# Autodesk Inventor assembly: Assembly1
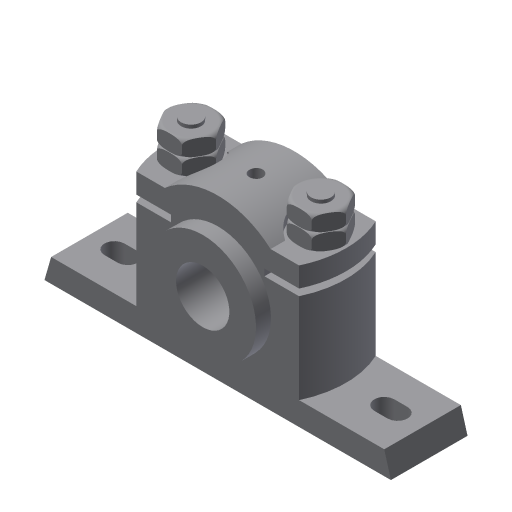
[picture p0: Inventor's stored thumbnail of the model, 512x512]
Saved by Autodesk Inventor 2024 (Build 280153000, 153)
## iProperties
Created: 2016-03
Part Number: Assembly1
Document SubType Name: Assembly
Designer: Sandeep
Author: Sandeep
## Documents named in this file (7)
- D:\PROJECTS\Project 2023\RESOURCES INVENTOR 2024\RESOURCES INVENTOR 2024\Inventor_2023_Part\Inventor_2024_Part\c13_Inv_2024_prt\fig-13-7\Plummer block assy\Assembly1.iam
- D:\PROJECTS\Project 2023\RESOURCES INVENTOR 2024\RESOURCES INVENTOR 2024\Inventor_2023_Part\Inventor_2024_Part\c13_Inv_2024_prt\fig-13-7\Plummer block assy\Casting.ipt
- D:\PROJECTS\Project 2023\RESOURCES INVENTOR 2024\RESOURCES INVENTOR 2024\Inventor_2023_Part\Inventor_2024_Part\c13_Inv_2024_prt\fig-13-7\Plummer block assy\Brasses.ipt
- D:\PROJECTS\Project 2023\RESOURCES INVENTOR 2024\RESOURCES INVENTOR 2024\Inventor_2023_Part\Inventor_2024_Part\c13_Inv_2024_prt\fig-13-7\Plummer block assy\Cap.ipt
- D:\PROJECTS\Project 2023\RESOURCES INVENTOR 2024\RESOURCES INVENTOR 2024\Inventor_2023_Part\Inventor_2024_Part\c13_Inv_2024_prt\fig-13-7\Plummer block assy\Bolt.ipt
- D:\PROJECTS\Project 2023\RESOURCES INVENTOR 2024\RESOURCES INVENTOR 2024\Inventor_2023_Part\Inventor_2024_Part\c13_Inv_2024_prt\fig-13-7\Plummer block assy\Nut.ipt
- D:\PROJECTS\Project 2023\RESOURCES INVENTOR 2024\RESOURCES INVENTOR 2024\Inventor_2023_Part\Inventor_2024_Part\c13_Inv_2024_prt\fig-13-7\Plummer block assy\Lock Nut.ipt
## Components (9 placed, 6 different names)
1. Casting:1 — Mate:1, Mate:2, Insert:1, Insert:2, Angle:1, Angle:2
2. Brasses:1 — Mate:1, Mate:2, Mate:3, Mate:4
3. Cap:1 — Mate:3, Mate:4, Insert:3, Insert:5
4. Bolt:1 — Insert:1, Angle:1
5. Bolt:2 — Insert:2, Angle:2
6. Nut:1 — Insert:3, Insert:4
7. Nut:2 — Insert:5, Insert:6
8. Lock Nut:1 — Insert:4
9. Lock Nut:2 — Insert:6
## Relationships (12: Insert 6, Mate 4, Angle 2)
- Mate:1: Casting:1 ↔ Brasses:1
- Mate:2: Casting:1 ↔ Brasses:1
- Mate:3: Brasses:1 ↔ Cap:1
- Mate:4: Brasses:1 ↔ Cap:1
- Insert:1: Casting:1 ↔ Bolt:1
- Insert:2: Casting:1 ↔ Bolt:2
- Angle:1: Casting:1 ↔ Bolt:1
- Angle:2: Casting:1 ↔ Bolt:2
- Insert:3: Cap:1 ↔ Nut:1
- Insert:4: Nut:1 ↔ Lock Nut:1
- Insert:5: Cap:1 ↔ Nut:2
- Insert:6: Nut:2 ↔ Lock Nut:2
